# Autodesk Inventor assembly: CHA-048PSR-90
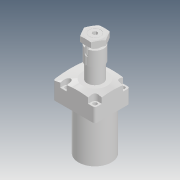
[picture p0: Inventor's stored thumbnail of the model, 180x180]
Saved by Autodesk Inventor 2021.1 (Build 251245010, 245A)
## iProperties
Created: 2018-12
Part Number: CHA-048PSR-90
Description: STEP AP214
Document SubType Name: Assembly
Designer: user
Title: CHA-048PSR.STEP
Revision Number: ÈÎºÎ
Sending System: SolidWorks 2016
Preprocessor: SwSTEP 2.0
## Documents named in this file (7)
- D:\Vault_2016\Projekty\Clamptek\Hydraulic\CHA-P\Inventor\CHA-048PSR-90\CHA-048PSR-90.iam
- D:\Vault_2016\Projekty\Clamptek\Hydraulic\CHA-P\Inventor\CHA-048PSR-90\CHA-048P(BT).ipt
- D:\Vault_2016\Projekty\Clamptek\Hydraulic\CHA-P\Inventor\CHA-048PSR-90\CHA-048P(LM).ipt
- D:\Vault_2016\Projekty\Clamptek\Hydraulic\CHA-P\Inventor\CHA-048PSR-90\XIAO.ipt
- D:\Vault_2016\Projekty\Clamptek\Hydraulic\CHA-P\Inventor\CHA-048PSR-90\¶ÂÍ·G8-1.ipt
- D:\Vault_2016\Projekty\Clamptek\Hydraulic\CHA-P\Inventor\CHA-048PSR-90\CHA-048PS(HSG).ipt
- D:\Vault_2016\Projekty\Clamptek\Hydraulic\CHA-P\Inventor\CHA-048PSR-90\CHA-048PS(HSGZH).ipt
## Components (7 placed, 7 different names)
1. CHA-048P(BT)_1
2. CHA-048P(LM)_2
3. XIAO_3
4. ¶ÂÍ·G8-1_4
5. CHA-048PS(HSG)_5
6. CHA-048PS(HSGZH)_6
7. ¶ÂÍ·G8-1_7
